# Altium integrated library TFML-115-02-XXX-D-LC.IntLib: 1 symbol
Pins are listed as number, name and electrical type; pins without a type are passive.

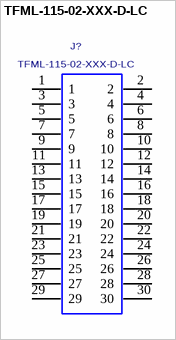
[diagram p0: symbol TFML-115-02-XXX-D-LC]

## TFML-115-02-XXX-D-LC
designator J?
0.050" PITCH SHROUDED TERMINAL ASSEMBLY.; MANUFACTURER: SAMTEC
footprint TFML-115-02-XXX-D-LC
pins: 1, 2, 3, 4, 5, 6, 7, 8, 9, 10, 11, 12, 13, 14, 15, 16, 17, 18, 19, 20, 21, 22, 23, 24, 25, 26, 27, 28, 29, 30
